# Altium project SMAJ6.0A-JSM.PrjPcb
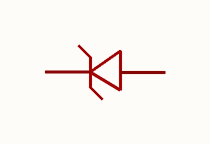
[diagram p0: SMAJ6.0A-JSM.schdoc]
1 sheet, 1 parts. Net scope: global (net labels, ports and power ports of the same name join across sheets).

## Sheet SMAJ6.0A-JSM.schdoc
size 127 x 101 mm

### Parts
D?  smaj6.0a-jsm  [SMA_L4.3-W2.6-LS5.2-RD]  (value not drawn)

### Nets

Not connected (* = marked no-connect by the designer): D? 1(C) 2(A)

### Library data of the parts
D? = smaj6.0a-jsm: 极性:单向;反向截止电压(Vrwm):6V;钳位电压:10.3V;峰值脉冲电流(Ipp):38.8A;峰值脉冲功率(Ppp):400W;击穿电压(VBR):7.37V;; Manufacturer: JSMSEMI(杰盛微); AddInBom: yes; ModelId: e3551acb3c5a4975a5e9d36087fe1fa2; ModelTransform: 185.039,102.362,0,0,0,0,0,0,0; Polarity: 单向; Reverse Stand-Off Voltage (Vrwm): 6V; Clamping Voltage: 10.3V; Peak Pulse Current (Ipp): 38.8A; Peak Pulse Power Dissipation (Ppp): 400W; Voltage - Breakdown: 7.37V; Reverse Leakage Current (Ir): 800uA; Number of Channels: 单路; Type: TVS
